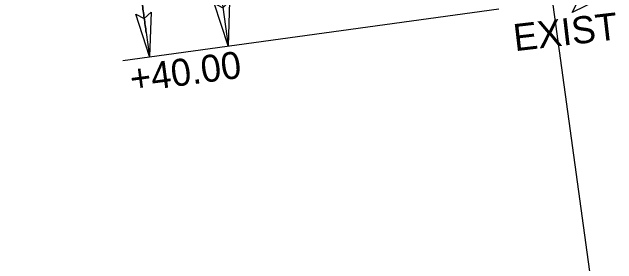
# Model space of a CAD drawing. Extents: x 1778969 to 1790720, y 807089 to 817794.
# Drawn here: x 1780914.3 to 1781025.9, y 811056.9 to 811103.4 of the extents above; entities that cross this region are included whole.
import ezdxf

# ---------------------------------------------------------------- set-up
doc = ezdxf.new("R2010")
doc.units = 0
for name, color, linetype in [('Prop Dimension', 7, 'Continuous'), ('Prop Dimension Text', 7, 'Continuous'), ('Prop Horizontal Alignment', 7, 'Continuous'), ('Prop Superelevation  Arrow CELL', 7, 'Continuous'), ('Prop Superelevation Label', 7, 'Continuous'), ('Prop Terminator CELL', 7, 'Continuous')]:
    doc.layers.add(name, color=color, linetype=linetype)

msp = doc.modelspace()

# ---------------------------------------------------------------- linework, layer by layer
at = {"layer": 'Prop Dimension'}
for p, q in [((1780948.7, 811136.88), (1780954.15, 811097.2)), ((1780934.72, 811094.53), (1781004.07, 811104.05)), ((1780939.06, 811099.65), (1780939.67, 811095.21)), ((1780939.06, 811099.65), (1780939.67, 811095.21))]:
    msp.add_line(p, q, dxfattribs=at)
for points in [[(1780939.06, 811099.65), (1780938.69, 811102.33), (1780938.32, 811105.01), (1780937.96, 811107.69), (1780937.59, 811110.37), (1780937.22, 811113.06), (1780936.85, 811115.74), (1780936.48, 811118.42), (1780936.12, 811121.11), (1780935.75, 811123.8), (1780935.38, 811126.49), (1780935.02, 811129.18), (1780934.65, 811131.87), (1780934.28, 811134.56), (1780933.92, 811137.26), (1780933.55, 811139.95), (1780933.19, 811142.65), (1780932.82, 811145.34), (1780932.46, 811148.04), (1780932.09, 811150.74), (1780931.73, 811153.44), (1780931.37, 811156.15), (1780931.01, 811158.85), (1780930.65, 811161.56), (1780930.29, 811164.26), (1780929.93, 811166.97), (1780929.57, 811169.68), (1780929.21, 811172.39), (1780928.86, 811175.1), (1780928.5, 811177.82), (1780928.15, 811180.53), (1780927.8, 811183.25), (1780927.44, 811185.96), (1780927.09, 811188.68), (1780926.75, 811191.4), (1780926.4, 811194.12), (1780926.05, 811196.84), (1780925.71, 811199.57), (1780925.36, 811202.29), (1780925.02, 811205.02), (1780924.68, 811207.75), (1780924.34, 811210.48), (1780924, 811213.21), (1780923.67, 811215.94), (1780923.33, 811218.67), (1780923, 811221.41), (1780922.67, 811224.14), (1780922.34, 811226.88), (1780922.01, 811229.62), (1780921.69, 811232.36), (1780921.37, 811235.1), (1780921.05, 811237.85), (1780920.73, 811240.59), (1780920.41, 811243.34), (1780920.09, 811246.09), (1780919.78, 811248.84), (1780919.47, 811251.59), (1780919.16, 811254.34), (1780918.86, 811257.09), (1780918.56, 811259.85), (1780918.25, 811262.6), (1780917.96, 811265.36), (1780917.66, 811268.12), (1780917.37, 811270.88), (1780917.08, 811273.64), (1780916.79, 811276.41), (1780916.5, 811279.17), (1780916.22, 811281.94), (1780915.94, 811284.7), (1780915.66, 811287.47), (1780915.39, 811290.25), (1780915.12, 811293.02), (1780914.85, 811295.79), (1780914.58, 811298.57), (1780914.33, 811301.3)], [(1780914.33, 811301.3), (1780914.58, 811298.57), (1780914.85, 811295.79), (1780915.12, 811293.02), (1780915.39, 811290.25), (1780915.66, 811287.47), (1780915.94, 811284.7), (1780916.22, 811281.94), (1780916.5, 811279.17), (1780916.79, 811276.41), (1780917.08, 811273.64), (1780917.37, 811270.88), (1780917.66, 811268.12), (1780917.96, 811265.36), (1780918.25, 811262.6), (1780918.56, 811259.85), (1780918.86, 811257.09), (1780919.16, 811254.34), (1780919.47, 811251.59), (1780919.78, 811248.84), (1780920.09, 811246.09), (1780920.41, 811243.34), (1780920.73, 811240.59), (1780921.05, 811237.85), (1780921.37, 811235.1), (1780921.69, 811232.36), (1780922.01, 811229.62), (1780922.34, 811226.88), (1780922.67, 811224.14), (1780923, 811221.41), (1780923.33, 811218.67), (1780923.67, 811215.94), (1780924, 811213.21), (1780924.34, 811210.48), (1780924.68, 811207.75), (1780925.02, 811205.02), (1780925.36, 811202.29), (1780925.71, 811199.57), (1780926.05, 811196.84), (1780926.4, 811194.12), (1780926.75, 811191.4), (1780927.09, 811188.68), (1780927.44, 811185.96), (1780927.8, 811183.25), (1780928.15, 811180.53), (1780928.5, 811177.82), (1780928.86, 811175.1), (1780929.21, 811172.39), (1780929.57, 811169.68), (1780929.93, 811166.97), (1780930.29, 811164.26), (1780930.65, 811161.56), (1780931.01, 811158.85), (1780931.37, 811156.15), (1780931.73, 811153.44), (1780932.09, 811150.74), (1780932.46, 811148.04), (1780932.82, 811145.34), (1780933.19, 811142.65), (1780933.55, 811139.95), (1780933.92, 811137.26), (1780934.28, 811134.56), (1780934.65, 811131.87), (1780935.02, 811129.18), (1780935.38, 811126.49), (1780935.75, 811123.8), (1780936.12, 811121.11), (1780936.48, 811118.42), (1780936.85, 811115.74), (1780937.22, 811113.06), (1780937.59, 811110.37), (1780937.96, 811107.69), (1780938.32, 811105.01), (1780938.69, 811102.33), (1780939.06, 811099.65)]]:
    msp.add_spline(points, degree=3, dxfattribs=at)
at = {"layer": 'Prop Horizontal Alignment'}
msp.add_line((1781013.36, 811109.85), (1781025.87, 811018.76), dxfattribs=at)
at = {"layer": 'Prop Superelevation  Arrow CELL'}
msp.add_lwpolyline([(1781024.72, 811106.89), (1781017.63, 811103.39), (1781018.99, 811106.1)], close=True, dxfattribs=at)
at = {"layer": 'Prop Terminator CELL'}
for points in [[(1780954.43, 811105.41), (1780954.15, 811097.2), (1780951.61, 811105.07), (1780953.18, 811104.24)], [(1780939.95, 811103.42), (1780939.67, 811095.21), (1780937.14, 811103.08), (1780938.7, 811102.25)]]:
    msp.add_lwpolyline(points, close=True, dxfattribs=at)

# ---------------------------------------------------------------- texts
at = {"layer": 'Prop Dimension Text'}
msp.add_text('+40.00', height=5, rotation=7.6835, dxfattribs=at).set_placement((1780936.39, 811088.58))
at = {"layer": 'Prop Superelevation Label'}
msp.add_text('EXIST', height=5, rotation=6.6484, dxfattribs=at).set_placement((1781007.07, 811096.2))

doc.saveas('drawing.dxf')
